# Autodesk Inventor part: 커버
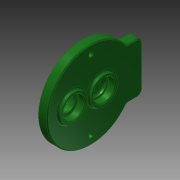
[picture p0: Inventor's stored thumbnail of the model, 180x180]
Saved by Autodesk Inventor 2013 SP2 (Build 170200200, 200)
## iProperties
Created: 2016-02
Part Number: 커버
Material: 알루미늄 6061
Document SubType Name: Modeling
Designer: mduedu
Density: 2.71 g/cm^3
Author: mduedu
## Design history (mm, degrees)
sketch "스케치1"
  geometry: C1 r 45 at (0, 0); 1 further point
  constraints: 1 centre point, 1 coincident
  dimensions: "d0" = 90 diameter of C1
extrude "돌출1" new body sketch "스케치1" distance "d1" = 9; taper "d2" = 0 deg
sketch "스케치2"
  geometry: C1 r 14 at (0, 11); 1 further point
  constraints: 1 centre point, 1 vertical alignment
  dimensions: "d3" = 28 diameter of C1; "d6" = 11 distance of C1.centre point (0, 0)
extrude "돌출2" join sketch "스케치2" distance "d7" = 3; taper "d8" = 0 deg
sketch "스케치3"
  geometry: C1 r 14 at (0, -20); 1 further point
  constraints: 1 centre point, 1 vertical alignment
  dimensions: "d9" = 28 diameter of C1; "d10" = 20 distance of C1.centre point (0, 0)
extrude "돌출3" join sketch "스케치3" distance "d11" = 3; taper "d12" = 0 deg
hole "구멍1" diameter "d15" = 22; stored, may be unused: countersink angle "d19" = 90 deg, drill point angle "d21" = 0 deg; dims "d13" = 10, "d14" = 10, "d16" = 6, "d17" = 4, "d18" = 2, "d20" = 7
hole "구멍2" diameter "d24" = 18; stored, may be unused: countersink angle "d28" = 90 deg, drill point angle "d30" = 0 deg; dims "d25" = 6, "d26" = 4, "d27" = 2, "d29" = 3, "d107" = 10, "d108" = 10
hole "구멍3" diameter "d33" = 22; stored, may be unused: countersink angle "d37" = 90 deg, drill point angle "d39" = 0 deg; dims "d34" = 6, "d35" = 4, "d36" = 2, "d38" = 7, "d73" = 10, "d74" = 10
sketch "스케치7"
  geometry: L1 (-26, 36.729)-(26, 36.729); L2 (26, 36.729)-(26, 53); L3 (26, 53)-(-26, 53); L4 (-26, 53)-(-26, 36.729); A1 r 45 centre (0, 0) between (-26, 36.729) and (26, 36.729) reference; 1 further point
  constraints: 8 end point, 2 parallel, 2 point on circle, 1 horizontal, 1 perpendicular
  dimensions: "d95" = 52 distance of L2.end L3.end; "d97" = 53 distance from line of L3 point (0, 0)
extrude "돌출5" join sketch "스케치7" stored distance "d98" = 10; taper "d99" = 0 deg
sketch "스케치4"
  geometry: C1 r 14 at (0, -20) reference; C2 r 18 at (0, -20); 1 further point
  constraints: 1 centre point, 1 coincident
  dimensions: "d40" = 36 diameter of C2
extrude "돌출4" join sketch "스케치4" distance "d41" = 4; taper "d42" = 0 deg
hole "구멍4" diameter "d45" = 22; stored, may be unused: countersink angle "d49" = 90 deg, drill point angle "d51" = 0 deg; dims "d46" = 6, "d47" = 4, "d48" = 2, "d50" = 7.3, "d102" = 10, "d103" = 10
chamfer "모따기3" distance "d104" = 0.7; stored, may be unused: second distance "d105" = 2, angle "d106" = 30 deg
hole "구멍5" diameter "d54" = 15; stored, may be unused: countersink angle "d58" = 90 deg, drill point angle "d60" = 0 deg; dims "d52" = 10, "d53" = 10, "d55" = 6, "d56" = 4, "d57" = 2, "d59" = 7
fillet "모깎기1" dims "d61" = 0.3
fillet "모깎기2" dims "d62" = 3
chamfer "모따기1" distance "d63" = 1; stored, may be unused: second distance "d64" = 2, angle "d65" = 45 deg
fillet "모깎기6" dims "d88" = 2
sketch "스케치5" dims "d67" = 72
  geometry: 4 further points
  constraints: 2 horizontal alignment, 1 coincident, 5 other
  dimensions: "d71" = 360 deg dimension on point (0, 0) point (-36, 0) (derived)
fillet "모깎기4" dims "d75" = 2
sketch "스케치6"
  geometry: 2 further points
hole "구멍6" sketch "스케치6" at (36, 0), (-36, 0) diameter "d76" = 4.5; stored, may be unused: countersink angle "d80" = 90 deg, drill point angle "d82" = 0 deg; dims "d77" = 6, "d78" = 8, "d79" = 4.6, "d81" = 8
fillet "모깎기7" dims "d100" = 6, "d101" = 3
chamfer "모따기2" distance "d90" = 1; stored, may be unused: second distance "d91" = 2, angle "d92" = 45 deg
node "솔리드1"
node "절단 모서리 투영1"
